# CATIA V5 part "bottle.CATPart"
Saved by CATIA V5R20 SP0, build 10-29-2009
Part number: 饮料瓶
Material "DS Light Blue": density 7860 kg/m3, Young's modulus 2e+11 Pa, Poisson ratio 0.266
Material "Cloudy Sky"
Material "Fire Red": density 7860 kg/m3, Young's modulus 2e+11 Pa, Poisson ratio 0.266
Bounding box of the stored display mesh (mm): x -25 to 26, y -25 to 25, z 0 to 110
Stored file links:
  C:\Users\DELL\Desktop\王浩\bottle.CATPart
  E:\CATIA\win_b64\startup\materials\Catalog.CATMaterial
  E:\CATIA\win_b64\startup\materials\DS_star.jpg
  E:\CATIA\win_b64\startup\materials\chessboard.jpg
  E:\CATIA\win_b64\startup\materials\no_skid.jpg
  E:\CATIA\win_b64\startup\materials\blue_env_512x512.jpg
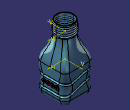
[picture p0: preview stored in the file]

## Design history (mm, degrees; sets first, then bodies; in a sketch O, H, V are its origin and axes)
Set1
  Sketch1 on xy-plane, origin (0, 0, 0), H (1, 0, 0), V (0, 1, 0)
    point P1 (0, 0)
    line L1 (25, 25) -> (25, -25)
    line L2 (25, -25) -> (-25, -25)
    line L3 (-25, -25) -> (-25, 25)
    line L4 (-25, 25) -> (25, 25)
    length L1 = 50
    length L4 = 50
    coincidence: P1 V, P1 H
    vertical: L1 V, L3 V
    horizontal: L2 H, L4 H
    equidistance: L1 L3 P1, L2 L4 P1
  Sketch2 on face of Pad1 from Sketch1.L2, origin (0, -25, 0), H (1, 0, 0), V (0, 0, 1)
    spline S1 through (-48.822, 0) (-10.1473, 23.8211) (12.744, 16.6738) (57.9052, 27.3431)
    point P1 (-48.822, 0)
    coincidence: P1 H
  Extrude1: Element1 Sketch2, Lim1 60, Lim2 60
  MultiSel1: CommonCtxFeats ({extract ExtractElem face of Pad1 from Sketch1.L4}; {extract ExtractElem face of Fillet1}; {extract ExtractElem face of Pad1 from Sketch1.L3}; {extract ExtractElem face of Fillet1}; {extract ExtractElem face of Pad1 from Sketch1.L2}; {extract ExtractElem face of Fillet1}; {extract ExtractElem face of Pad1 from Sketch1.L1}; {extract ExtractElem face of Fillet1})
  Sketch3 on face of Pad1 from Sketch1.L2, origin (0, -25, 0), H (1, 0, 0), V (0, 0, 1)
    spline S1 through (-34.0063, 29.5181) (-13.3283, 38.6631) (8.749, 33.2381) (34.5577, 36.0281)
  Extrude2: Element1 Sketch3, Lim1 60, Lim2 60
  MultiSel2: CommonCtxFeats ({extract ExtractElem face of Pad1 from Sketch1.L2}; {extract ExtractElem face of Fillet1}; {extract ExtractElem face of Pad1 from Sketch1.L1}; {extract ExtractElem face of Fillet1}; {extract ExtractElem face of Pad1 from Sketch1.L4}; {extract ExtractElem face of Fillet1}; {extract ExtractElem face of Pad1 from Sketch1.L3}; {extract ExtractElem face of Fillet1})
  Join1: Elements ({intersect ToIntersect1 {extract ExtractElem face of Pad1 from Sketch1.L2}, ToIntersect2 Extrude2}; {intersect ToIntersect1 {extract ExtractElem face of Fillet1}, ToIntersect2 Extrude2}; {intersect ToIntersect1 {extract ExtractElem face of Pad1 from Sketch1.L1}, ToIntersect2 Extrude2}; {intersect ToIntersect1 {extract ExtractElem face of Fillet1}, ToIntersect2 Extrude2}; {intersect ToIntersect1 {extract ExtractElem face of Pad1 from Sketch1.L4}, ToIntersect2 Extrude2}; {intersect ToIntersect1 {extract ExtractElem face of Fillet1}, ToIntersect2 Extrude2}; {intersect ToIntersect1 {extract ExtractElem face of Pad1 from Sketch1.L3}, ToIntersect2 Extrude2}; {intersect ToIntersect1 {extract ExtractElem face of Fillet1}, ToIntersect2 Extrude2})
  Join2: Elements {intersect ToIntersect1 Fillet1, ToIntersect2 Extrude1}
  Join3: Elements ({intersect ToIntersect1 {extract ExtractElem face of Pad1 from Sketch1.L4}, ToIntersect2 Extrude1}; {intersect ToIntersect1 {extract ExtractElem face of Fillet1}, ToIntersect2 Extrude1}; {intersect ToIntersect1 {extract ExtractElem face of Pad1 from Sketch1.L3}, ToIntersect2 Extrude1}; {intersect ToIntersect1 {extract ExtractElem face of Fillet1}, ToIntersect2 Extrude1}; {intersect ToIntersect1 {extract ExtractElem face of Pad1 from Sketch1.L2}, ToIntersect2 Extrude1}; {intersect ToIntersect1 {extract ExtractElem face of Fillet1}, ToIntersect2 Extrude1}; {intersect ToIntersect1 {extract ExtractElem face of Pad1 from Sketch1.L1}, ToIntersect2 Extrude1}; {intersect ToIntersect1 {extract ExtractElem face of Fillet1}, ToIntersect2 Extrude1})
  Plane1: type Normal, Curve Join3, RefPoint vertex [face of MultiSel1 | face of MultiSel1]
  Circle1: type CtrRad, Start 0, End 180, Center vertex [face of MultiSel1 | face of MultiSel1], Support Plane1, Radius 2, FirstDirection (0, 1, 0)
  Plane2: type Normal, Curve Join1, RefPoint vertex [face of MultiSel2 | face of MultiSel2]
  Circle2: type CtrRad, Start 0, End 180, Center vertex [face of MultiSel2 | face of MultiSel2], Support Plane2, Radius 2, FirstDirection (0, 1, 0)
Body1 (main body), material "DS Light Blue"
  Pad1: profile Sketch1, direction (0, 0, 1), length 50
  Fillet1: on edge [face of Pad1 from Sketch1.L4 | face of Pad1 from Sketch1.L1]; edge [face of Pad1 from Sketch1.L3 | face of Pad1 from Sketch1.L4]; edge [face of Pad1 from Sketch1.L1 | face of Pad1 from Sketch1.L2]; edge [face of Pad1 from Sketch1.L2 | face of Pad1 from Sketch1.L3]
  Fillet2: radius 8, on start face of Pad1
  Plane3: type Offset, RefPlane end face of Pad1, Offset 40, reversed
  Sketch4 on Plane3, origin (0, 0, 90), H (1, 0, 0), V (0, -1, 0)
    circle A1 centre (0, 0) radius 15
  Pad2: profile Sketch4, direction (0, 0, 1), length 20
  Sketch5 on start face of Pad2, origin (0, 0, 90), H (1, 0, 0), V (0, -1, 0)
    point P1 (15, 0)
    distance P1 V = 15
    coincidence: P1 H
  Sketch6 on end face of Pad1, origin (0, 0, 50), H (1, 0, 0), V (0, 1, 0)
    point P1 (25, 0)
    distance P1 V = 25
    coincidence: P1 H
  Sketch7 on end face of Pad1, origin (0, 0, 50), H (1, 0, 0), V (0, 1, 0)
  Loft1: solid, Sections ({boundary Boundary {extract ExtractElem end face of Pad1}}; {boundary Boundary {extract ExtractElem start face of Pad2}}), StartFace end face of Pad1, EndFace start face of Pad2
  Slot1: profile Circle2, centre curve Join1
  Slot2: profile Circle1, centre curve Join3
  Shell1: IntOffset 1, Face end face of Pad2, ExtOffset 0
  Plane4: type Offset, RefPlane Plane3, Offset 2, reversed
  Sketch8 on Plane4, origin (0, 0, 92), H (1, 0, 0), V (0, -1, 0)
  Sketch9 on Plane4, origin (0, 0, 92), H (1, 0, 0), V (0, -1, 0)
    point P1 (15, 0)
    distance P1 V = 15
    coincidence: P1 H
  Helix1: Direction Z axis, RefPoint Sketch9, Pitch 3, Height 16, TaperAngle 0
  Point1: type OnCurve, Support Helix1, RefPoint vertex of Helix1, Length -5
  Point2: type OnCurve, Support Helix1, RefPoint Sketch9, Length -5
  Line1: type PtDir, RefPoint vertex of Helix1, Direction (0, 1, 0), Start 0, End 10
Body2, material "Cloudy Sky"
  Connect1: Curve1 Line1, Point1 vertex of Line1, Tension1 1, Curve2 Helix1, Point2 Point1, Tension2 1
  Line2: type PtDir, RefPoint Sketch9, Direction (1, 0, 0), Start 0, End -10
  Connect2: Curve1 Line2, Point1 vertex of Line2, Tension1 1, Curve2 Connect1, Point2 Point2, Tension2 1
  Plane5: type Normal, Curve Connect2, RefPoint vertex of Connect1
  Circle3: type CtrRad, Start 0, End 180, Center vertex of Connect1, Support Plane5, Radius 1, FirstDirection (1, 0, 0)
  Plane6: type Normal, Curve Connect2, RefPoint vertex of Connect2
  Circle4: type CtrRad, Start 0, End 180, Center vertex of Connect2, Support Plane6, Radius 1, FirstDirection (0, 1, 0)
  Rib1: profile Circle4, centre curve Connect2
  Sketch10 on xy-plane, origin (0, 0, 0), H (1, 0, 0), V (0, 1, 0)
    circle A1 centre (0, 0) radius 14
    radius A1 = 14
  Body3
    Plane7: type Offset, RefPlane xy-plane, Offset 80
    Sketch11 on Plane7, origin (0, 0, 80), H (1, 0, 0), V (0, 1, 0)
      circle A1 centre (0, 0) radius 14
    Pad3: profile Sketch11, direction (0, 0, 1), length 30
  Remove1: tool Body3
Body4, material "Fire Red"
  Sketch12 on face of Pad1 from Sketch1.L1, origin (25, 0, 0), H (0, 1, 0), V (0, 0, 1)
    polyline C1
    polyline C2
    polyline C3
    polyline C4
    polyline C5
    polyline C6
  Pad4: profile Sketch12, direction (1, 0, 0), length 1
